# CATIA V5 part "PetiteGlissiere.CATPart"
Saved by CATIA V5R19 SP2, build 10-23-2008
Part number: PetiteGlissiere
Bounding box of the stored display mesh (mm): x 0 to 10, y -80 to 60, z -20 to 40
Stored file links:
  D:\SCHOOL\FRANCE\BANC_POUTRE_EN_MOUSSE\PetiteGlissiere.CATPart
  C:\Program Files\Dassault Systemes\B19\intel_a\reffiles\standard\MetricThickPitch.txt
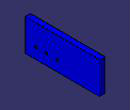
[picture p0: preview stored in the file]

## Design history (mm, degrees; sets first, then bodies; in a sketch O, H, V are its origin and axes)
AxisSystem1: origin (0, 0, 0), X (1, 0, 0), Y (0, 1, 0), Z (0, 0, 1)
Body1 (main body)
  Sketch1 on YZ plane of AxisSystem1, origin (0, 0, 0), H (0, 1, 0), V (0, 0, 1)
    line L1 (80, 20) -> (80, -20)
    line L2 (80, -20) -> (-80, -20)
    line L3 (-80, -20) -> (-80, 20)
    line L4 (-80, 20) -> (80, 20)
    length L4 = 160
    length L1 = 40
    vertical: L1 V, L3 V
    horizontal: L2 H, L4 H
    equidistance: L1 L3 O, L2 L4 O
  Pad1: profile Sketch1, direction (1, 0, 0), length 10
  Sketch2 on start face of Pad1, origin (0, -57.8553, -24.1337), H (0, 1, 0), V (0, 0, -1)
    point P1 (-2.1447, -24.1337)
    reference projected line E1 (-22.1447, -64.1337) -> (-22.1447, 15.8663) from edge [start face of Pad1 | face of Pad1 from Sketch1.L3]
    reference projected line E2 (-12.1447, -4.1337) -> (127.8553, -4.1337) from edge [start face of Pad1 | face of Pad1 from Sketch1.L2]
    distance E1 P1 = 20
    distance E2 P1 = 20
  Hole1: placed by Sketch2, at (0, -60, 0) direction (1, 0, 0), diameter 4.917, through (limit type 3), counterbore diameter 10, counterbore depth 5
  RectPattern1: of Hole1, direction 1 instances 2, spacing 40, along edge [start face of Pad1 | face of Pad1 from Sketch1.L4] reversed
  Sketch3 on start face of Pad1, origin (0, -57.9977, -0.2981), H (0, 1, 0), V (0, 0, -1)
    point P1 (17.9977, -0.2981)
    axis line L1 (-70.0023, -0.2981) -> (159.9977, -0.2981)
    reference projected line E1 (-22.0023, -40.2981) -> (-22.0023, 39.7019) from edge [start face of Pad1 | face of Pad1 from Sketch1.L3]
    reference intersected line E2 through (0, -0.2981) direction (1, 0) from XY plane of AxisSystem1
    distance E1 P1 = 40
    horizontal: L1 H
    coincidence: L1 P1, E2 L1
  Hole2: placed by Sketch3, at (0, -40, 0) direction (1, 0, 0), diameter 4.917, through (limit type 3), counterbore diameter 10, counterbore depth 5
  Sketch4 on face of Pad1 from Sketch1.L4, origin (0, 0, 20), H (1, 0, 0), V (0, 1, 0)
  Pad2: profile Sketch4, direction (0, 0, 1), length 20
  Sketch5 on face of Pad2, origin (10, -56.6363, 73.8877), H (0, 1, 0), V (0, 0, 1)
    point P1 (9.2363, -43.8877)
    reference projected line E1 (-23.3637, -33.8877) -> (136.6363, -33.8877) from edge [face of Pad2 | end face of Pad2]
    reference projected line E2 (-23.3637, -53.8877) -> (-23.3637, -93.8877) from edge [face of Pad2 | face of Pad2]
    distance E1 P1 = 10
    distance E2 P1 = 32.6
  Sketch6 on face of Pad1 from Sketch1.L2, origin (0, 0, -20), H (1, 0, 0), V (0, -1, 0)
    line L1 (0, -60) -> (10, -60)
    projected line E1 (0, 80) -> (0, -80) from edge [face of Pad2 | face of Pad1 from Sketch1.L2]
    projected line E2 (0, -60) -> (0, -80) from edge [face of Pad2 | face of Pad1 from Sketch1.L2]
    point P2 (0, -80)
    projected line E3 (0, -80) -> (10, -80) from edge [face of Pad2 | face of Pad1 from Sketch1.L2]
    point P3 (0, -80)
    point P4 (10, -80)
    projected line E4 (10, 80) -> (10, -80) from edge [face of Pad1 from Sketch1.L2 | face of Pad2]
    projected line E5 (10, -60) -> (10, -80) from edge [face of Pad1 from Sketch1.L2 | face of Pad2]
    point P6 (10, -80)
    point P7 (10, -60)
    point P8 (0, -60)
    distance E3 L1 = 20
    horizontal: L1 H
    coincidence: E4 P7, E1 P8, P2 P3, P4 P6
  Pocket1: profile Sketch6, direction (0, 0, 1), through (limit type 6)
  Sketch7 on face of Pad2, origin (0, 46.5135, 3.6081), H (0, 1, 0), V (0, 0, -1)
    point P1 (-1.5135, 8.6081)
    reference projected line E1 (-126.5135, 23.6081) -> (33.4865, 23.6081) from edge [face of Pad2 | face of Pad1 from Sketch1.L2]
    reference projected line E2 (13.4865, 23.6081) -> (13.4865, -36.3919) from edge [face of Pad2 | face of Pocket1 from Sketch6.L1]
    distance E1 P1 = 15
    distance E2 P1 = 15
  Hole3: placed by Sketch7, at (0, 45, -5) direction (1, 0, 0), diameter 10.106, depth 8, threaded "M12", thread diameter 12, thread depth 8, pitch 1.75
  RectPattern2: of Hole3, direction 1 instances 2, spacing 110, along edge [face of Pad2 | face of Pad1 from Sketch1.L2] reversed, direction 2 instances 2, spacing 30, along edge [face of Pad2 | face of Pocket1 from Sketch6.L1]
